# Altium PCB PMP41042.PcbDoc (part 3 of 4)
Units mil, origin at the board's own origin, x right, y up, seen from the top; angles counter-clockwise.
Board outline 9847.6 x 4445 mil, 6 copper layers (Top Layer, Layer 1, Layer 2, Layer 3, Layer 4, Bottom Layer), stack 32.112 mil thick; 329 components, 129 nets, 1246 pads, 863 vias.
Unrouted connection lines stored in the file: 6.
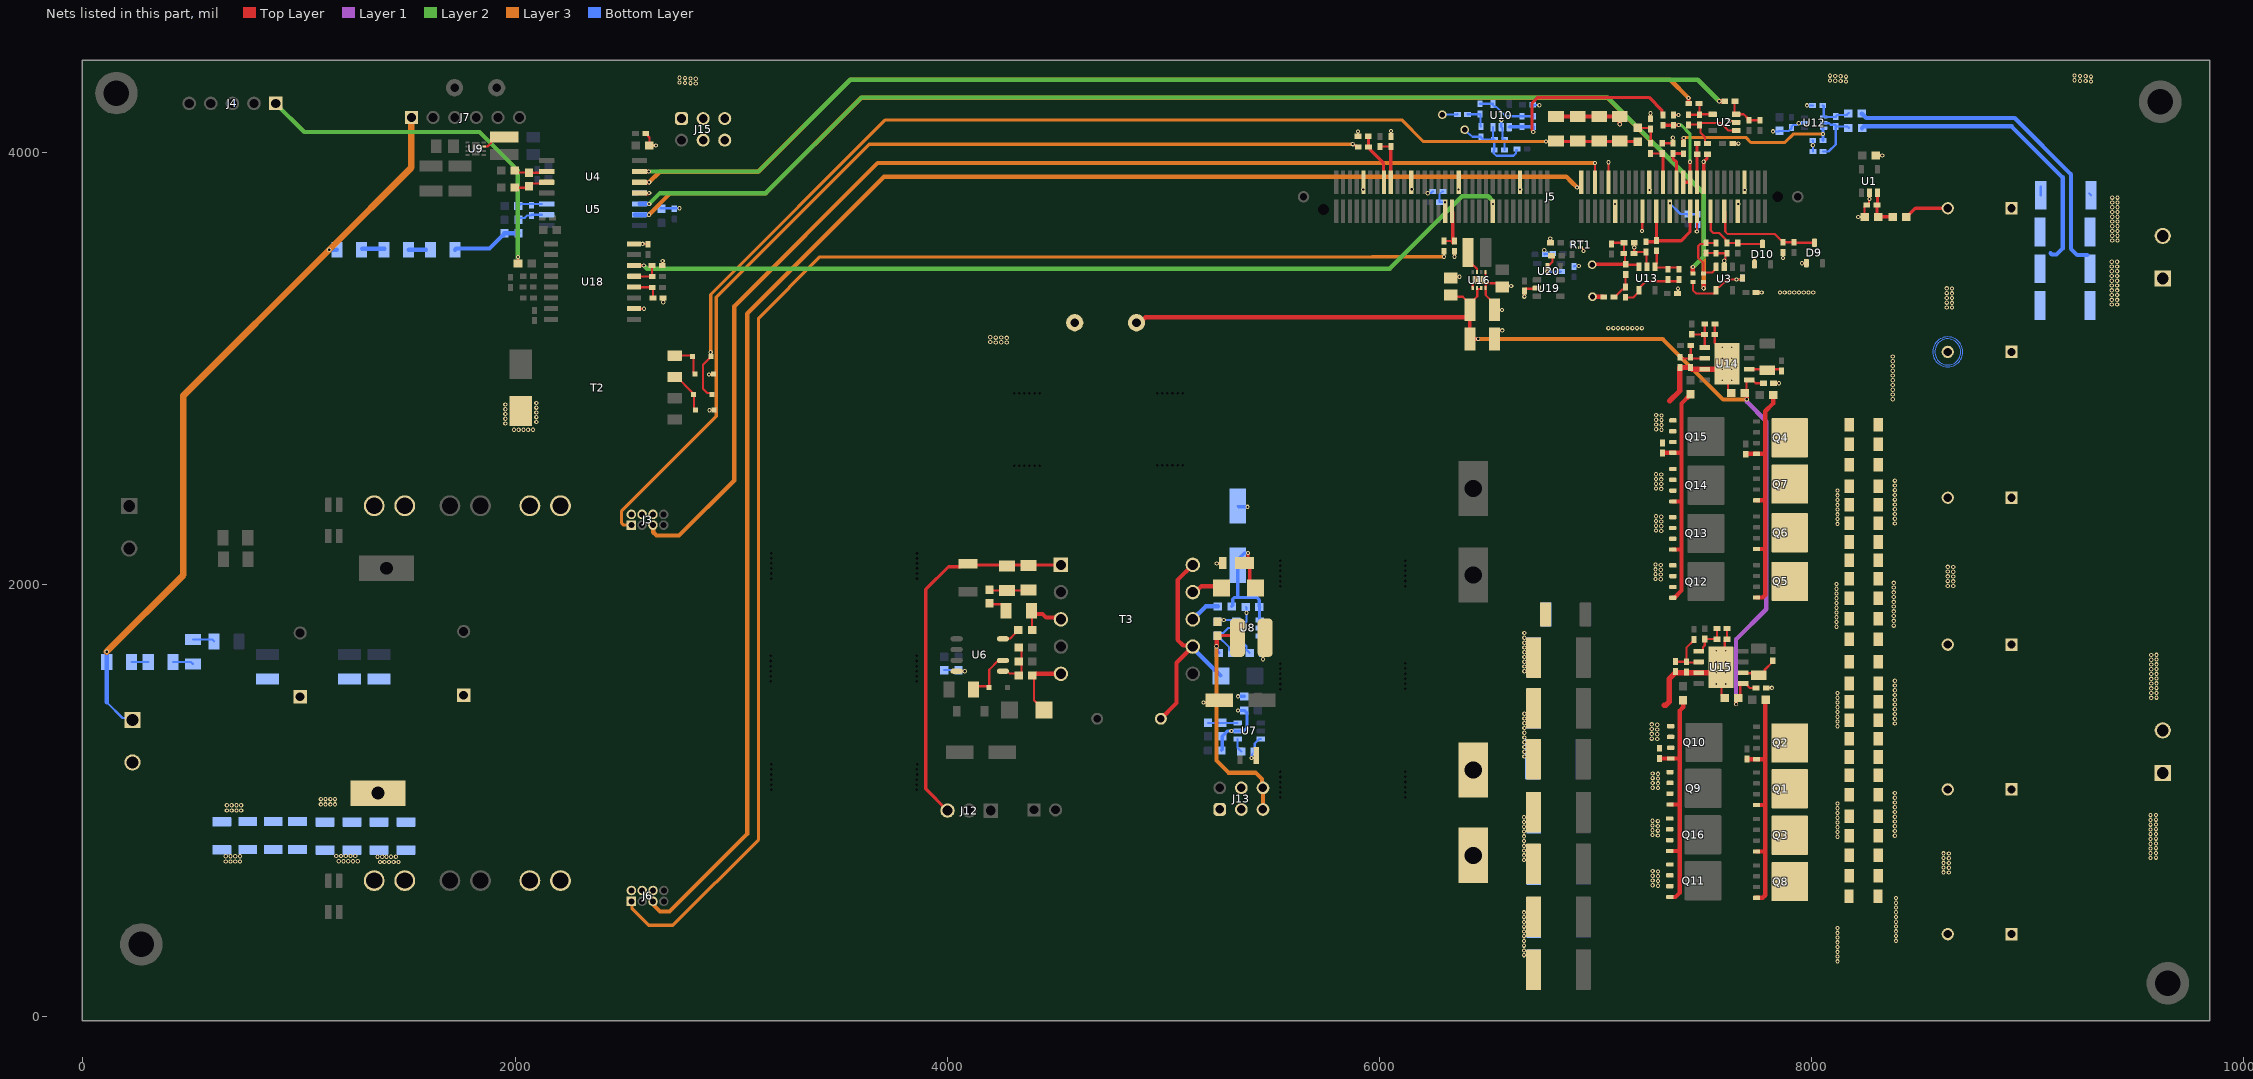
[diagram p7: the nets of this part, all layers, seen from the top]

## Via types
v1: diameter 19.68, hole 10, Top Layer to Bottom Layer, tented both sides, 821 vias
v2: diameter 19.68, hole 7.87, Top Layer to Bottom Layer, 12 vias
v3: diameter 19.68, hole 12, Top Layer to Bottom Layer, tented both sides, 11 vias
v4: diameter 20, hole 10, Top Layer to Bottom Layer, tented both sides, 11 vias
v5: diameter 19.68, hole 7.87, Top Layer to Bottom Layer, tented both sides, 8 vias

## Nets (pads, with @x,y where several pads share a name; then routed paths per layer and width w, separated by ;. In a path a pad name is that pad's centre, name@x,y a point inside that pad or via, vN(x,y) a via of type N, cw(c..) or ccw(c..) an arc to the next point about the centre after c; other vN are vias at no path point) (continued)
12Vs: 12Vs.1 C83.1 C102.2 C104.2 C115.2 C117.2 C128.2 C129.2 C130.1 J13.5 J13.6 J15.5 J15.6 L3.2 R43.2 U14.1 U15.1 U16.2 U16.3 | length 6313.6
  Top Layer w10: C130.1@6334.09,3352.28 6354.09,3332.28 6386.65,3332.28 C128.2@6419.09,3299.84 ; C129.2@6419.09,3138.11 C129.2@6419.92,3137.28 ; C128.2@6419.09,3262.87 C128.2@6419.09,3272.28 C128.2@6419.09,3299.84 ; U16.3@6471.49,3368.54 6453.7,3368.54 6453.7,3334.45 C128.2@6419.09,3299.84 ; C115.2@7651.5,1464.69 C115.2@7661.5,1474.69 7671.06,1484.25 7671.06,1533.86 7676.89,1539.69 7698.62,1539.69 7704.45,1533.86 7704.45,1531.34 7713.5,1522.28 C117.2@7744.25,1522.28 ; C102.2@7701.5,2877.28 C102.2@7691.5,2887.28 7699.41,2895.2 7699.41,2941.46 7705.24,2947.28 U14.1@7713.19,2947.28 7726.97,2947.28 7741.97,2932.28 C104.2@7777.87,2932.28
  Top Layer w15: v3(5246.61,1714.33) v3@5247.51,1715.22 ; R43.2@5247.51,1760.22 R43.2@5251.61,1764.33 5323.66,1764.33 L3.2@5343.66,1744.33 ; C129.2@6419.09,3138.11 C128.2@6419.09,3262.87
  Top Layer w20: 12Vs.1@4876.5,3212.28 4892.73,3212.28 4917.73,3237.28 6403.5,3237.28 6419.09,3252.87 C128.2@6419.09,3272.28 ; v3@5247.51,1715.22 R43.2@5247.51,1760.22 ; C129.2@6419.92,3137.28 v3(6457.32,3137.28) ; v3(7651.5,1447.28) C115.2@7651.5,1464.69 ; v3(7701.5,2857.28) C102.2@7701.5,2877.28
  Layer 1 w20: v3(7651.5,1447.28) 7651.5,1746.5 7791.5,1886.5 7791.5,2756.26 7701.5,2846.26 v3(7701.5,2857.28)
  Layer 3 w20: v3(5246.61,1714.33) 5246.61,1185.65 5302.26,1130 5427.26,1130 5457.26,1100 5457.26,1063.68 J13.6@5461.61,1059.33 J13.5@5461.61,959.33 ; v3(6457.32,3137.28) 7311.5,3137.28 7591.5,2857.28 v3(7701.5,2857.28)
  Bottom Layer w15: v3(5246.61,1714.33) v3@5247.51,1713.43 ; C83.1@5247.51,1693.43 C83.1@5256.61,1684.33
  Bottom Layer w20: C83.1@5247.51,1693.43 v3@5247.51,1713.43
18V: C68.1 C69.1 C81.1 D5.1 D7.1 U8.4 U8.5 | length 710.7
  Top Layer w15: v1(5392,2147) 5392,2114.72 D7.1@5376.61,2099.33 5376.79,2099.33 5400.35,2075.77 D5.1@5400.35,1984.33
  Bottom Layer w15: C69.1@5316.45,1899.33 5321.61,1904.49 5321.61,1932.65 5329.96,1941 5346,1941 ; v1(5392,2147) 5377.4,2147 5345,2114.6 C68.1@5345,2090.19 5345,1942 5346,1941 ; C81.1@5444.96,1899.33 5444.96,1929.04 5433,1941 5346,1941 ; C81.1@5445.5,1897 C81.1@5446.28,1896.21 ; U8.5@5445.74,1799.33 U8.4@5445.74,1836.73 C81.1@5445.74,1898.54
48Vo+: C41.1 C44.1 C46.1 C47.1 C48.1 C49.1 C50.1 C51.1 C52.1 C53.1 C54.1 C55.1 C56.1 C57.1 C58.2 C59.2 C60.1 C61.2 C62.2 C63.2 C64.2 C76.1 C77.1 C87.1 C163.1 C164.1 C186.1 C187.1 C188.1 C189.1 C190.1 J10.1 J10.2 Q1.5 Q1.6 Q1.7 Q1.8 Q1.9@7900.04,1055.16 Q2.5 Q2.6 Q2.7 Q2.8 Q2.9@7900.04,1267.28 Q3.5 Q3.6 Q3.7 Q3.8 Q3.9@7900.04,840.16 Q4.5 Q4.6 Q4.7 Q4.8 Q4.9@7900.04,2680.16 Q5.5 Q5.6 Q5.7 Q5.8 Q5.9@7900.04,2015.16 Q6.5 Q6.6 Q6.7 Q6.8 Q6.9@7900.04,2240.16 Q7.5 Q7.6 Q7.7 Q7.8 Q7.9@7900.04,2465.16 Q8.5 Q8.6 Q8.7 Q8.8 Q8.9@7900.04,625.16 R3.2 | length 195.6
  Top Layer w15: R3.2@8449.62,3710.41 8449.62,3711.43 8454.17,3715.98 8455.2,3715.98 8481.5,3742.28 C59.2@8631.46,3742.28
  other v1: 8121.5,256.23 8121.5,278.24 8121.5,300.24 8121.5,322.25 8121.5,344.26 8121.5,366.27 8121.5,388.28 8121.5,410.28 8636.5,667.28 8611.5,668.27 8636.5,689.29 8611.5,690.28 8636.5,711.3 8611.5,712.28 8636.5,733.31 8611.5,734.29 9570,734.99 9595.5,736.24 8636.5,755.32 8611.5,756.3 9570,757 9595.5,758.24 9570,779.01 9595.5,780.25 9570,801.02 9595.5,802.26 9570,823.02 9595.5,824.27 8121.5,833.23 9570,845.03 9595.5,846.28 8121.5,855.24 9570,867.04 9595.5,868.28 8121.5,877.24 9570,889.05 9595.5,890.29 8121.5,899.25 9570,911.06 9595.5,912.3 8121.5,921.26 9570,933.06 9595.5,934.31 8121.5,943.27 8121.5,965.28 8121.5,987.28 8121.5,1344.25 8121.5,1366.26 8121.5,1388.27 8121.5,1410.28 8121.5,1432.28 8121.5,1454.29 8121.5,1476.3 9573,1475.98 9598,1476.98 8121.5,1498.31 9573,1497.99 9598,1498.99 9573,1520 9598,1521 9573,1542.01 9598,1543.01 9573,1564.02 9598,1565.02 9573,1586.02 9598,1587.02 9573,1608.03 9598,1609.03 9573,1630.04 9598,1631.04 9573,1652.05 9598,1653.05 9573,1674.06 9598,1675.06 8116.5,1805.28 8116.5,1827.28 8116.5,1849.29 8116.5,1871.3 8116.5,1893.31 8116.5,1915.32 8116.5,1937.32 8116.5,1959.33 8116.5,1981.34 8656.5,1993.27 8631.5,1994.25 8116.5,2003.35 8656.5,2015.28 8631.5,2016.26 8656.5,2037.28 8631.5,2038.27 8656.5,2059.29 8631.5,2060.28 8656.5,2081.3 8631.5,2082.28 8121.5,2281.26 8121.5,2303.27 8121.5,2325.28 8121.5,2347.28 8121.5,2369.29 8121.5,2391.3 8121.5,2413.31 8121.5,2435.32 8651.5,3282.28 8626.5,3283.27 8651.5,3304.29 8626.5,3305.28 8651.5,3326.3 8626.5,3327.28 8651.5,3348.31 8626.5,3349.29 8651.5,3370.32 8626.5,3371.3
48Vo-: J11.1 J11.2 R46.2 R49.2 R50.2 R54.2 R72.1 | length 1528.7
  Bottom Layer w10: R50.2@9285.47,3810.91 R50.2@9294.09,3802.28
  Bottom Layer w20: R72.1@8233,4180 8233.98,4180 8253.98,4160 8941,4160 9202,3899 9202,3554 9230,3526 R46.2@9276.55,3526
  other v1: 9390.47,3296.22 9415.47,3296.22 9390.47,3318.23 9415.47,3318.23 9390.47,3340.24 9415.47,3340.24 9390.47,3362.24 9415.47,3362.24 9390.47,3384.25 9415.47,3384.25 9390.47,3406.26 9415.47,3406.26 9390.47,3428.27 9415.47,3428.27 9390.47,3450.28 9415.47,3450.28 9390.47,3472.28 9415.47,3472.28 9390.47,3494.29 9415.47,3494.29 9392.6,3593.11 9417.6,3593.11 9392.6,3615.12 9417.6,3615.12 9392.6,3637.13 9417.6,3637.13 9392.6,3659.13 9417.6,3659.13 9392.6,3681.14 9417.6,3681.14 9392.6,3703.15 9417.6,3703.15 9392.6,3725.16 9417.6,3725.16 9392.6,3747.17 9417.6,3747.17 9392.6,3769.17 9417.6,3769.17 9392.6,3791.18 9417.6,3791.18
Bot_FET_FAULT1: J3.1 R102.1 | length 4538.5
  Top Layer w10: v1(5877,4038.84) 5878.78,4038.84 5885.22,4032.4 5892.58,4032.4 R102.1@5896.29,4028.69
  Layer 3 w15: J3.1@2537.99,2275.39 2537.62,2275.77 2502.23,2275.77 2493,2285 2493,2341 2931.5,2779.5 2931.5,3330.5 3639,4038 5876.16,4038 v1(5877,4038.84)
Bot_FET_FAULT2: J6.1 R97.1 | length 6548.7
  Top Layer w10: v1(6300,3517.44) R97.1@6300,3543.03
  Layer 3 w15: J6.1@2538.39,535.24 2541.52,532.1 2541.52,499.48 2618,423 2730,423 3127,820 3127,3234 3410,3517 5967.46,3517 5967.9,3517.44 v1(6300,3517.44)
Bot_FET_PWM1: J3.5 J5.51 | length 5674.4
  Top Layer w10: J5.51@6998.03,3862.28 v1(6998,3952)
  Layer 3 w20: J3.5@2637.99,2275.39 2639.1,2274.28 2639.1,2242.9 2654.8,2227.2 2758.8,2227.2 3014,2482.4 3014,3288 3678,3952 v1(6998,3952)
Bot_FET_PWM2: J5.55 J6.5 | length 7184.1
  Top Layer w15: v1(6916,3838) 6916.9,3838.9 6925.43,3838.9 6935.04,3848.51 J5.55@6935.04,3862.28
  Layer 3 w20: J6.5@2638.39,535.24 2643,530.63 2643,514.72 2670.72,487 2715,487 3074,846 3074,3254 3708,3888 6866,3888 6888.93,3865.07 v1(6916,3838)
COIL_PRI_N: C132.2 C133.1 pad.1@6395,4106 R55.1 R58.2 U10.3 | length 424.4
  Bottom Layer w10: pad.1@6395,4106 6396.57,4101.18 6397.31,4098.9 6399.56,4096.65 6431.61,4073.38 C132.2@6471,4073.38 6471,4069.44 6480.44,4060 C133.1@6527,4060 ; U10.3@6527,4117.73 C133.1@6527,4060 ; C133.1@6530.38,4051 6527,4054.38 C133.1@6527,4060 ; R55.1@6638,4011 6632.86,4011 6632.24,4010.38 6632.24,3996.24 6621,3985 6542,3985 6530,3997 6530,4009.62 R58.2@6532.38,4012 6532.38,4051 6532.38,4059 C133.1@6533.38,4060 C133.1@6527,4060
COIL_PRI_P: pad.1@6292,4175 R56.1 | length 70.6
  Bottom Layer w10: pad.1@6292,4175 6293,4176 6360.76,4176 R56.1@6361.76,4177
COIL_SEC_N: C89.1 C95.2 pad.1@6985,3481 R30.1 R31.2 U13.3 | length 366
  Top Layer w10: 7088.94,3582.28 C89.1@7133.23,3582.28 7133.23,3533.66 R31.2@7131.85,3532.28 7137.28,3526.85 C95.2@7137.28,3490 ; C95.2@7137.28,3480.91 7194.88,3480.91 7201.69,3474.09 U13.3@7201.69,3471.42
  Top Layer w15: pad.1@6985,3481 6986.62,3482.62 7137.28,3482.62 C95.2@7141,3482.62
COIL_SEC_P: pad.1@6987,3333 R66.1 | length 52.2
  Top Layer w10: pad.1@6987.62,3333 pad.1@6988.62,3332 ; R66.1@7038,3332 R66.1@7039,3331
  Top Layer w20: pad.1@6988.62,3332 R66.1@7038,3332
DGND: C3.2 C18.2 C26.2 C32.2 C33.2 C34.2 C37.2 C38.2 C39.2 C41.2 C44.2 C45.2 C46.2 C47.2 C48.2 C49.2 C50.2 C51.2 C52.2 C53.2 C54.2 C55.2 C56.2 C57.2 C58.1 C59.1 C60.2 C61.1 C62.1 C63.1 C64.1 C68.2 C69.2 C71.2 C72.2 C76.2 C77.2 C80.2 C81.2 C82.2 C83.2 C87.2 C89.2 C92.1 C93.1 C94.1 C97.2 C98.2 C99.2 C100.2 C102.1 C103.1 C104.1 C107.2 C108.2 C109.1 C110.2 C111.1 C112.1 C114.1 C115.1 C116.2 C117.1 C122.2 C123.2 C125.1 C126.2 C127.2 C128.1 C129.1 C130.2 C131.2 C133.2 C134.2 C135.2 C139.1 C140.1 C142.2 C143.2 C144.2 C145.2 C146.2 C149.2 C150.2 C151.2 C163.2 C164.2 C186.2 C187.2 C188.2 C189.2 C190.2 D3.2 D4.2 D7.2 D9.1 D10.1 DGND.1 J3.2 J3.4 J3.6 J5.7 J5.10 J5.19 J5.22 J5.35 J5.38 J5.46 J5.47 J5.65 J5.83 J5.97 J5.111 J6.2 J6.4 J6.6 J13.1 J13.3 J13.4 J15.1 J15.3 J15.4 Q9.1 Q9.2 Q9.3 Q10.1 Q10.2 Q10.3 Q11.1 Q11.2 Q11.3 Q12.1 Q12.2 Q12.3 Q13.1 Q13.2 Q13.3 Q14.1 Q14.2 Q14.3 Q15.1 Q15.2 Q15.3 Q16.1 Q16.2 Q16.3 R5.1 R10.1 R11.1 R12.1 R13.1 R29.1 R31.1 R44.1 R45.1 R46.1 R49.1 R50.1 R51.1 R52.1 R54.1 R58.1 R70.1 R79.1 R82.1 R92.1 R93.1 RT1.1 T3.8 U1.2 U2.2 U3.2 U4.5 U5.5 U7.2 U8.2 U10.2 U12.2 U13.2 U14.7 U14.9@7609.84,3022.28 U15.7 U15.9@7581.5,1617.28 U16.1 U16.4 U16.5 U16.9@6461.97,3409.88 U18.2 U18.8 U19.2 U20.2 | length 8376.9
  Top Layer w10: U18.2@2551.02,3277.28 v1(2596.5,3277.28) ; U18.8@2551.02,3577.28 v1(2590.47,3577.28) 2615.47,3577.28 C140.1@2615.47,3575.91 ; U4.5@2570.04,3807.28 2615.47,3807.28 v1(2620.47,3812.28) ; C38.2@2600.47,4087.28 C38.2@2604.41,4087.28 ; C38.2@2611.13,4094 C38.2@2604.41,4087.28 ; C32.2@2625.08,4029.69 C32.2@2632.6,4029.69 ; v1(2651.5,4032.28) 2635.94,4032.28 2633.35,4034.88 2630.75,4032.28 C32.2@2621.97,4032.28 2621.97,4069.72 C38.2@2604.41,4087.28 ; C146.2@2681.5,3477.28 2683,3478.79 v1(2683,3498) ; C145.2@2685.12,3327.28 2685.47,3326.93 v1(2685.47,3307.28) ; v1(2898,2973) 2899,2974 2917.61,2974 D4.2@2918.61,2975 ; v1(2900,2807) 2901,2808 2914.53,2808 D3.2@2916.81,2810.28 ; v1(5186.61,1454.33) 5249.76,1454.33 C71.2@5259.76,1464.33 ; v1(5248,2098) 5274.89,2098 D7.2@5276.22,2099.33 ; v1(5901,4097) 5901,4076.09 C135.2@5901.5,4075.59 ; v1(5926,3829) 5926.58,3829.58 5926.58,3861.7 J5.111@5927.17,3862.28 ; C134.2@6054.09,4074.53 v1(6054.09,4100.12) ; J5.97@6147.64,3862.28 6148.82,3861.1 6148.82,3831.18 v1(6150,3830) ; C130.2@6330,3420 6335.34,3425.34 v1(6371.38,3425.34) ; v1(6348.19,3517.44) C127.2@6348.19,3543.03 ; v1(6367,3829) 6367.56,3829.56 6367.56,3861.73 J5.83@6368.11,3862.28 ; U16.1@6432.44,3372.48 6432.52,3372.56 6432.52,3394.21 U16.9@6444.25,3405.94 ; U16.9@6469.09,3402.28 U16.9@6471.11,3404.3 ; v2(6483.62,3409.88) 6483.62,3417.76 6491.42,3425.55 6491.42,3447.2 U16.5@6491.5,3447.28 ; U16.9@6485.28,3402.56 U16.9@6485.28,3394.69 ; U16.4@6492.99,3379.09 6492.99,3386.97 U16.9@6485.28,3394.69 ; U16.4@6493.07,3379.02 6493.07,3357.36 6493.15,3357.28 6493.15,3339.96 6533.27,3299.84 C128.1@6533.27,3272.28 6534.55,3271 v1(6568,3271) ; C129.1@6534.09,3137.28 6534.09,3156.41 6554.69,3177 v1(6569,3177) ; v1(6610.47,3382.28) 6574.09,3382.28 C131.2@6569.09,3377.28 6551.69,3394.69 U16.9@6485.28,3394.69 ; J5.65@6651.57,3862.28 6651.79,3862.07 6651.79,3829.21 v1(6652,3829) ; v1(6671.5,3333.07) C144.2@6671.5,3358.66 6671.5,3362.6 6678.31,3369.41 6727.09,3369.41 U19.2@6729.96,3372.28 ; v1(6778,3447) 6778,3471.88 6777.6,3472.28 6778.58,3472.28 6801.5,3495.2 C143.2@6801.5,3522.28 ; v1(6791.5,3602.28) 6791.5,3583.66 C97.2@6792.87,3582.28 ; RT1.1@6931.5,3559.49 6933.39,3557.6 6938.31,3557.6 6943.15,3552.76 6943.15,3545.85 v1(6945,3544) ; v1(7060.69,3955) 7060.85,3954.83 7060.85,3862.45 J5.47@7061.02,3862.28 ; v1(7091.5,3762.28) 7092.01,3761.77 7092.01,3728.94 J5.46@7092.52,3728.43 ; C89.2@7180.47,3582.28 v1(7180.47,3560.63) 7180.47,3533.66 R31.1@7179.09,3532.28 7183.03,3532.28 7190.47,3539.72 C116.2@7234.09,3539.72 7236.59,3537.22 7236.59,3473.92 U13.2@7239.09,3471.42 ; v1(7216.5,3637.28) 7217.5,3638.29 7217.5,3727.42 J5.38@7218.5,3728.43 ; J5.35@7250,3862.28 7250.75,3861.54 7250.75,3828.03 v1(7251.5,3827.28) ; C26.2@7256,4156.62 v1(7256,4182.21) ; C139.1@7310,4043.21 C110.2@7358.97,4043.21 ; C110.2@7359,4043.24 v1(7359,4068.83) ; C109.1@7362.65,4173.24 7363.41,4174 v1(7385,4174) ; C94.1@7380.12,3347.28 7383,3350.17 v1(7383,3370) ; v1(7470,3635) 7470.24,3635.24 7470.24,3728.19 J5.22@7470.47,3728.43 ; R29.1@7504.69,3538.66 7511.5,3531.85 R29.1@7511.5,3530.04 ; R29.1@7511.65,3535.32 7557.44,3535.32 C45.2@7559.09,3533.66 C112.1@7609.09,3533.66 7602.28,3526.85 7602.28,3507.31 7596.69,3501.72 v1(7596.69,3499.09) U3.2@7596.69,3470.55 ; R82.1@7553.74,3207.28 7552.52,3206.06 C107.2@7552.52,3157.28 7552.52,3117.99 7571.46,3099.06 v5(7588.19,3099.06) ; U15.9@7581.5,1617.28 7583.82,1614.96 7583.82,1488.39 7597.52,1474.69 C115.1@7598.5,1474.69 ; v5(7603.15,1694.06) 7599.37,1697.83 7599.37,1740.47 7606.18,1747.28 R93.1@7610.12,1747.28 C122.2@7610.12,1797.28 ; v1(7621.5,4147.28) 7623.35,4145.43 7645.75,4145.43 U2.2@7651.5,4139.69 ; C102.1@7628.5,2887.28 7627.52,2887.28 7613.82,2900.98 7613.82,2930.83 7628.5,2945.51 v5(7631.5,2945.51) ; C34.2@7636.5,4042.28 7637.09,4041.69 7661.49,4041.69 v1(7662.09,4041.09) ; J5.10@7659.45,3728.43 7660.47,3729.45 7660.47,3761.26 v1(7661.5,3762.28) ; J5.7@7690.94,3862.28 7691.22,3862.01 7691.22,3827.56 v1(7691.5,3827.28) ; v1(7736.5,3512.28) 7736.59,3512.19 7736.59,3482.38 D10.1@7736.69,3482.28 ; C39.2@7744.29,3352.28 v1(7769.88,3352.28) ; C117.1@7791.5,1522.28 v1(7817.09,1522.28) ; C104.1@7825.12,2932.28 v1(7850.71,2932.28) ; v1(7869.09,3511.69) C114.1@7869.09,3537.28 ; v1(7956.5,3487.28) 7956.75,3487.54 7976.44,3487.54 D9.1@7976.69,3487.8 ; v1(8216.69,3701.59) R5.1@8246.22,3701.59 8246.22,3750.47 8253.03,3757.28 C18.2@8256.5,3757.28 8260.43,3757.28 8267.24,3764.09 8267.24,3783.4 v1(8268.62,3784.78) U1.2@8268.62,3813.33 ; C3.2@8298.54,3985.98 v1(8328.07,3985.98)
  Top Layer w15: v1(7501.5,3957.28) v1@7501.97,3956.81 ; J5.19@7501.97,3862.28 7501.73,3862.52 7501.73,3956.57 v1@7501.97,3956.81 ; C111.1@7518.74,3992.28 7516.49,3990.03 7516.49,3971.33 v1@7501.97,3956.81
  Top Layer w20: R10.1@6820,4164.95 R10.1@6818.28,4166.67 R12.1@6918.28,4166.67 R11.1@7018.28,4166.67 R13.1@7113.28,4166.67 7113,4166.39 v1(7113,4131)
  Top Layer w25: 7318,1442 7327.36,1442 7342,1456.64 7342,1563 7371.28,1592.28 U15.7@7478.15,1592.28 U15.9@7559.25,1592.28 ; 7344.08,2850.08 7391.5,2897.5 R79.1@7391.5,3005.04 C108.2@7441.5,3005.04 7441.5,3004.09 7448.31,2997.28 U14.7@7506.5,2997.28 7584.84,2997.28 U14.9@7609.84,3022.28
  Bottom Layer w0.5: 8691.59,3077.28 ccw(c8631.46,3077.28) 8691.59,3077.28 ; 8700.88,3077.28 ccw(c8631.46,3077.28) 8700.88,3077.28
  Bottom Layer w10: U5.5@2553.66,3812.28 U5.5@2575.47,3812.28 v1(2620.47,3812.28) ; C37.2@2672.47,3740.37 2674.39,3742.28 v1(2760.47,3742.28) ; C83.2@5319.6,1684.33 5318.62,1684.33 5304.92,1698.03 5304.92,1710.04 5251.61,1763.34 R45.1@5251.61,1764.33 5263.91,1776.63 5278.91,1776.63 5301.61,1799.33 U8.2@5337.48,1799.33 5343.6,1805.45 5362.88,1805.45 5385,1827.57 v1(5385,1870) 5385,1894.5 C81.2@5382.5,1897 ; C68.2@5345,2363.81 C68.2@5348.81,2360 ; v1(6224.22,3811.59) 6226.07,3813.45 6240.69,3813.45 6240.94,3813.19 C126.2@6247.76,3820 ; v1(6565,4150) 6564.7,4149.7 6564.7,4118.03 U10.2@6564.4,4117.73 6570,4112.13 6570,4066.81 6576.81,4060 C133.2@6580.62,4060 6579.62,4059 R58.1@6579.62,4012 ; C125.1@6710.24,4221 6711.24,4220 6740,4220 v1(6741,4219) ; v1(6763.86,3547.8) 6764.19,3547.46 6764.19,3529.43 6764.53,3529.09 6766.12,3530.69 6804.9,3530.69 C151.2@6806.5,3532.28 ; v1(6778,3447) 6779.44,3448.44 6838.32,3448.44 U20.2@6839.76,3449.88 ; C149.2@6901.5,3472.28 6904.21,3475 v1(6923,3475) ; v1(7470,3635) 7471.85,3636.85 7471.85,3665.04 C103.1@7474.09,3667.28 ; v1(7823,4098) 7850.21,4098 C93.1@7852.72,4100.5 7895.91,4100.5 7907.72,4112.31 C92.1@7907.72,4116.25 7907.72,4120.19 7914.53,4127 7931.22,4127 7940.16,4135.94 v1(7941.85,4135.94) 7965.55,4135.94 U12.2@7968.43,4138.81 ; v1(7979.88,4218.5) C99.2@8005.47,4218.5 C99.2@8006.2,4217.77 ; C98.2@8006.2,4055.23 8006.9,4054.52 v1(8006.9,4033.57) C100.2@8006.9,4004.64 ; R50.1@9061.81,3802.28 R50.1@9061.81,3843.62
  Bottom Layer w15: C82.2@5269.6,1232.87 5273.11,1236.38 R44.1@5273.11,1297.87 5273.11,1298.86 5286.81,1312.56 5287.79,1312.56 5298.11,1322.87 v1(5315.43,1322.87) U7.2@5343.97,1322.87 5373.11,1322.87 5388.11,1337.87 5388.11,1404.88 C80.2@5375.11,1417.87 v1(5345.59,1417.87) ; v1(5345.59,1482.87) C72.2@5375.11,1482.87 ; C68.2@5348.81,2360 v1(5390,2360)
  Bottom Layer w20: T3.8@5136.73,1839.33 5196.73,1899.33 C69.2@5253.46,1899.33 ; R70.1@8234.5,4113 8242.5,4121 8927,4121 9163,3885 9163,3556 9135,3528 9113,3528 9107,3534
  other v1: 8391.5,351.26 8391.5,373.27 8391.5,395.28 8391.5,417.28 8391.5,439.29 8391.5,461.3 8391.5,483.31 8391.5,505.32 8391.5,527.32 8391.5,549.33 7290.47,606.26 7265.47,608.23 7290.47,628.27 7265.47,630.24 7290.47,650.28 7265.47,652.24 7290.47,672.28 7265.47,674.25 8386.44,837.36 7289.45,839.25 7264.45,841.22 8386.44,859.37 7289.45,861.26 7264.45,863.23 8386.44,881.38 7289.45,883.27 7264.45,885.24 8386.44,903.38 7289.45,905.28 7264.45,907.24 8386.44,925.39 8386.44,947.4 8386.44,969.41 8386.44,991.42 8386.44,1013.42 8386.44,1035.43 7290.47,1058.27 7265.47,1060.24 7290.47,1080.28 7265.47,1082.24 7290.47,1102.28 7265.47,1104.25 7290.47,1124.29 7265.47,1126.26 7286.5,1285.28 7261.5,1287.24 7286.5,1307.28 7261.5,1309.25 7286.5,1329.29 7261.5,1331.26 7286.5,1351.3 7261.5,1353.27 8386.5,1357.24 8386.5,1379.25 8386.5,1401.26 8386.5,1423.27 8386.5,1445.28 8386.5,1467.28 8386.5,1489.29 8386.5,1511.3 8386.5,1533.31 8386.5,1555.32 8381.5,1810.28 8381.5,1832.28 8381.5,1854.29 8381.5,1876.3 8381.5,1898.31 8381.5,1920.32 8381.5,1942.32 8381.5,1964.33 8381.5,1986.34 8381.5,2008.35 7303.16,2024.69 7278.16,2026.66 7303.16,2046.7 7278.16,2048.67 7303.16,2068.71 7278.16,2070.67 7303.16,2090.71 7278.16,2092.68 7305.47,2248.27 7280.47,2250.24 7305.47,2270.28 7280.47,2272.24 8386.5,2283.27 7305.47,2292.28 7280.47,2294.25 8386.5,2305.28 7305.47,2314.29 7280.47,2316.26 8386.5,2327.28 8386.5,2349.29 8386.5,2371.3 8386.5,2393.31 8386.5,2415.32 8386.5,2437.32 7305.47,2443.27 7280.47,2445.24 8386.5,2459.33 7305.47,2465.28 7280.47,2467.24 8386.5,2481.34 7305.47,2487.28 7280.47,2489.25 7305.47,2509.29 7280.47,2511.26 7306.5,2717.28 7281.5,2719.25 7306.5,2739.29 7281.5,2741.26 7306.5,2761.3 7281.5,2763.27 7306.5,2783.31 7281.5,2785.28 8376.5,2858.23 8376.5,2880.24 8376.5,2902.24 8376.5,2924.25 8376.5,2946.26 8376.5,2968.27 8376.5,2990.28 8376.5,3012.28 8376.5,3034.29 8376.5,3056.3 4275.47,3120.28 4224.5,3121.28 4250.47,3122.24 4199.5,3123.25 4275.47,3142.28 4224.5,3143.29 4250.47,3144.25 4199.5,3145.26 7060.43,3187.28 7083.42,3187.28 7105.43,3187.28 7127.44,3187.28 7149.45,3187.28 7171.46,3187.28 7193.46,3187.28 7215.47,3187.28 7854.45,3352.28 7876.46,3352.28 7898.46,3352.28 7920.47,3352.28 7942.48,3352.28 7964.49,3352.28 7986.5,3352.28 8008.5,3352.28 2836.5,4319.28 2811.5,4321.25 2786.5,4322.28 2761.5,4324.25 8160.5,4329.28 9294.5,4329.28 8135.5,4331.25 9269.5,4331.25 8110.9,4332 9243.18,4332.62 8085.9,4333.96 9218.18,4334.59 2836.5,4341.29 2811.5,4343.26 2786.5,4344.29 2761.5,4346.26 8160.5,4351.29 9294.5,4351.29 8135.5,4353.26 9269.5,4353.26 8110.9,4354 9243.18,4354.63 8085.9,4355.97 9218.18,4356.6
  other v2: 7559.84,1591.69 7603.15,1591.69 7559.84,1642.87 7603.15,1642.87 7588.19,2996.69 7631.5,2996.69 7588.19,3047.87 7631.5,3047.87 6440.31,3409.88
  other v5: 7559.84,1540.51 7603.15,1540.51 7559.84,1694.06 7588.19,2945.51 7631.5,3099.06
GaN_SW1: GaN_SW1.1 T2.2
  other v1: 1994.45,2717.28 2016.46,2717.28 2038.46,2717.28 2060.47,2717.28 2082.48,2717.28 1955,2745.98 2098.46,2753.27 1955,2767.99 2098.46,2775.28 1955,2790 2098.46,2797.28 1955,2812.01 2098.46,2819.29 1955,2834.02 2098.46,2841.3
GaN_SW2: C1.1 C5.1 C9.1 C15.1 C90.1 C113.1 C118.1 C119.1 GaN_SW2.1
  other v1: 1374.98,716 1394.98,716 1415.99,716 1438,716 1460.01,716 660.98,719 682.99,719 705,719 727,719 1183.87,719.59 1205.87,719.59 1227.88,719.59 1249.89,719.59 1271.9,719.59 1363.13,740.41 1385.09,740.41 1405.09,740.41 1426.11,740.41 1448.12,740.41 660.98,743.02 682.99,743.02 705,743.02 727,743.02 1171.98,744 1193.98,744 1215.99,744 1238,744 1260.01,744
HVBUS: C8.HVBUS C11.1 C12.1 C13.1 C66.1 C67.1 C101.1 HVBUS1.1 HVBUS2.1 HVBUS.1 J1.HVBUS J7.1 J12.3 R1.2 R15.2 R32.2 T3.1 | length 5197.3
  Top Layer w15: J12.3@4001.61,954.33 3901,1054.94 3901,1977.86 4006.01,2082.87 4061.85,2082.87 4070.27,2091.3 T3.1@4506.49,2091.3
  Layer 3 w30: v3(110,1690) 465,2045 465,2875.43 v3(1139.57,3550) 1520.47,3930.91 J7.1@1520.47,4162.28
  Bottom Layer w10: 109.92,1455.08 182.55,1382.45 220.78,1382.45 J1.HVBUS@229.09,1374.13 ; R1.2@109.92,1642.28 R1.2@110,1642.36
  Bottom Layer w20: 109.92,1455.08 R1.2@109.92,1642.28 ; R1.2@110,1642.36 v3(110,1690) ; v3(1139.57,3550) R15.2@1175,3550
ISNS_PRI: C25.1 R14.2 R84.1 U2.1 | length 337.5
  Top Layer w10: C25.1@7431.5,4127.44 7433.46,4129.41 7479.53,4129.41 R14.2@7481.5,4127.44 ; R84.1@7518.74,4042.28 7514.8,4042.28 7507.99,4049.09 7507.99,4070.79 7486.5,4092.28 7486.5,4122.44 R14.2@7481.5,4127.44 ; U2.1@7644.09,4102.28 7615.08,4102.28 7580.08,4137.28 7488.31,4137.28 7481.5,4130.47 R14.2@7481.5,4127.44
ISNS_PRI_TANK: C124.1 R53.1 R85.2 U10.1 | length 935.6
  Top Layer w15: v1(6713,4095) 6713,4096.27 6707,4102.27 6707,4229 6733,4255 7249,4255 7308.34,4195.66 7308.34,4177.56 R85.2@7312.65,4173.24
  Bottom Layer w15: U10.1@6601.8,4117.73 6603.31,4119.24 6711.49,4119.24 R53.1@6713,4120.76 v1(6713,4095)
ISNS_PRI_TANK1: C26.1 R6.1 R59.1 | length 124.4
  Top Layer w10: R6.1@7196.28,4113.99 7251.39,4113.99 C26.1@7256,4109.38 7256.5,4108.88 7256.5,4047.5 R59.1@7257,4047
ISNS_SEC: C98.1 R86.1 U12.6 | length 752
  Top Layer w20: R86.1@7409,4041.24 v1(7409,4066.83)
  Layer 3 w15: v1@7409,4068.1 v1@7409,4069 ; v1@7409,4070 7697,4070 7720.44,4046.56 7877.43,4046.56 7916.53,4085.66 v1(8053.44,4085.66)
  Bottom Layer w15: C98.1@8053.44,4055.23 v1(8053.44,4085.66) U12.6@8053.44,4110.35
ISNS_SEC_TANK: C91.1 R64.2 R89.1 U13.1 | length 193.4
  Top Layer w10: R89.1@7284.09,3545.04 7284.09,3486.89 7276.5,3479.29 U13.1@7276.5,3471.42 7280.63,3467.28 7381.28,3467.28 7388.09,3460.47 C91.1@7388.09,3459.94
LLC_Fault: J5.74 U18.6 | length 4177.2
  Top Layer w10: J5.74@6525.59,3728.43 J5.74@6526.04,3728.88 ; J5.74@6526.04,3761.83 v1(6526.5,3762.28)
  Top Layer w15: U18.6@2551.02,3477.28 v1(2595.47,3477.28) ; J5.74@6526.04,3728.88 J5.74@6526.04,3761.83
  Layer 2 w20: v1(2595.47,3477.28) 2610.76,3462 6048,3462 6383.28,3797.28 6504.72,3797.28 6525.6,3776.4 6525.6,3763.18 v1(6526.5,3762.28)
NetC1_2: C1.2 C5.2 C9.2 C15.2 C90.2 C113.2 C118.2 C119.2 pad.2@1365.35,1035
  other v1: 665.98,954.97 687.99,954.97 710,954.97 732,954.98 665.98,978.98 687.99,978.98 710,978.98 732,979 1100.98,983 1122.99,983 1145,983 1167,983.02 1100.98,1007.02 1122.99,1007.02 1145,1007.02 1167,1007.03
NetC2_1: C2.1 C4.1 C6.1 C7.1 C10.1 C14.1 C16.1 C17.1 C19.1 C20.1 C21.1 C22.1 C23.1 C24.1 C27.1 C28.1 pad.2@6435,746.89 pad.2@6435,1141.73
  other v1: 6670.22,284.96 6670.22,306.96 6670.22,328.97 6670.22,350.98 6670.22,372.99 6670.22,395 6670.22,417 6670.22,439.01 6670.22,461.02 6670.22,483.03 6670.22,724.96 6670.22,746.96 6670.22,768.97 6670.22,790.98 6670.22,812.99 6670.22,835 6670.22,857 6670.22,879.01 6670.22,901.02 6670.22,923.03 6671.5,1204.21 6671.5,1226.22 6671.5,1248.23 6671.5,1270.24 6671.5,1292.24 6671.5,1314.25 6671.5,1336.26 6671.5,1358.27 6671.5,1380.28 6671.5,1402.28 6671.5,1599.21 6671.5,1621.22 6671.5,1643.23 6671.5,1665.24 6671.5,1687.24 6671.5,1709.25 6671.5,1731.26 6671.5,1754.25 6671.5,1776.26
NetC18_1: C18.1 R3.1 R5.2 U1.3 | length 182.5
  Top Layer w15: U1.3@8306.02,3813.33 8306.02,3759.57 C18.1@8303.74,3757.28 8303.74,3707.07 R5.2@8309.21,3701.59 8309.9,3702.28 R3.1@8376.5,3702.28
NetC25_2: C25.2 R14.1 R19.2 U2.4 | length 158.5
  Top Layer w10: C25.2@7431.5,4174.69 R14.1@7481.5,4174.69 ; R19.2@7480.12,4227.28 7481.5,4225.91 R14.1@7481.5,4174.69 ; U2.4@7535.83,4177.09 7483.9,4177.09 R14.1@7481.5,4174.69
NetC29_1: C29.1 R16.1 R23.2 U3.4 | length 296.8
  Top Layer w10: R23.2@7451.5,3397.28 7451.5,3362.28 7466.5,3347.28 U3.4@7548.52,3347.28 ; U3.4@7559.29,3370.16 7566.1,3376.97 7573.98,3376.97 7609.29,3412.28 v1(7653.62,3412.28) C29.1@7669.91,3412.28
  Bottom Layer w10: v1(7653.62,3412.28) 7675.12,3412.28 R16.1@7681.5,3418.66
NetC40_1: C40.1 R18.2 U4.2 | length 142.9
  Top Layer w10: R18.2@2001.5,3907.28 2063.2,3907.28 2064.24,3906.25 U4.2@2144,3906.25
NetC40_2: C40.2 R24.2 U4.3 | length 161.2
  Top Layer w10: R24.2@2011.69,3823.58 R24.2@1997.99,3837.28 2058.27,3837.28 C40.2@2063.9,3842.91 C40.2@2059.09,3847.72 ; C40.2@2077.23,3856.25 U4.3@2144,3856.25
NetC42_1: C42.1 R21.2 R25.2 U2.3 | length 188.5
  Top Layer w10: R21.2@7646.34,4237.28 7644.09,4235.04 7644.09,4177.09 U2.3@7651.5,4177.09 7686.69,4177.09 7704.09,4159.69 7704.09,4149.53 C42.1@7754.09,4149.53
NetC43_1: C43.1 R22.2 U5.2 | length 120.3
  Bottom Layer w10: R22.2@2010.47,3697.28 2043.66,3697.28 2054.52,3708.14 2071.33,3708.14 2075.47,3712.28 U5.2@2124.53,3712.28
NetC43_2: C43.2 R28.2 U5.3 | length 116.2
  Bottom Layer w10: R28.2@2015.47,3752.28 R28.2@2018.27,3755.08 ; R28.2@2015.47,3755.08 R28.2@2018.27,3755.08 ; R28.2@2018.43,3755.08 R28.2@2018.27,3755.08 ; U5.3@2124.53,3762.28 2025.47,3762.28 R28.2@2018.27,3755.08
NetC45_1: C45.1 R26.2 R29.2 U3.3 | length 303.8
  Top Layer w10: C45.1@7559.09,3580.91 7513.31,3580.91 R29.2@7511.65,3582.56 7506.38,3577.28 7486.5,3577.28 7476.5,3567.28 7476.5,3512.28 7501.5,3487.28 7501.5,3444.53 7541.14,3444.53 7559.29,3462.68 U3.3@7559.29,3470.55 U3.3@7559.29,3478.43
NetC65_1: C65.1 D12.2 T3.7 T3.10 | length 1056
  Top Layer w15: C65.1@4979.72,1367.43 C65.1@4990.43,1378.15
  Top Layer w20: C65.1@4989.25,1379.33 5061.86,1451.94 5061.86,1638.47 T3.7@5136.73,1713.34 5131.42,1718.65 5092.29,1718.65 5066.61,1744.33 5066.61,2021.18 T3.10@5136.73,2091.3
  Bottom Layer w10: T3.7@5136.73,1706.73 T3.7@5136.73,1713.34
  Bottom Layer w20: T3.7@5136.73,1706.73 D12.2@5264.13,1579.33
NetC66_2: C66.2 R32.1 R33.2 | length 182.9
  Top Layer w10: R33.2@4186.61,1972.32 4365.47,1972.32 C66.2@4368.3,1975.15
NetC73_1: C73.1 D11.1 U6.6 | length 254
  Top Layer w10: C73.1@4105.39,1514.33 4120.39,1529.33 4195,1529.33 4195,1606.44 4237.88,1649.33 U6.6@4258.3,1649.33
NetC74_1: C74.1 R41.2 U6.4 | length 134.9
  Top Layer w10: U6.4@4043.74,1599.33 v1(4081.61,1599.33)
  Bottom Layer w10: C74.1@3986.61,1604.33 R41.2@4051.61,1604.33 4056.61,1599.33 v1(4081.61,1599.33)
NetC75_1: C75.1 R34.1 R40.2 U6.5 | length 222.1
  Top Layer w10: U6.5@4258.3,1599.33 4277.7,1599.33 4287.7,1589.33 4332.32,1589.33 4342.32,1579.33 4343.3,1579.33 4343.46,1579.49 4343.46,1643.03 C75.1@4343.46,1708.03
NetC78_1: C78.1 L1.1 U7.6 | length 143.1
  Top Layer w10: v1(5408.11,1197.87) L1.1@5428.7,1197.87
  Top Layer w20: L1.1@5428.7,1197.87 5430.51,1199.68 L1.1@5430.51,1209.17
  Bottom Layer w8: v1(5408.11,1197.87) 5408.92,1198.68 5408.92,1213.17 C78.1@5423.62,1227.87
  Bottom Layer w10: C78.1@5423.62,1227.87 5423.62,1264.72 5444.37,1285.47 U7.6@5452.24,1285.47
NetC78_2: C78.2 U7.1 | length 65.5
  Bottom Layer w10: U7.1@5343.97,1285.47 5343.97,1244.52 5360.63,1227.87 C78.2@5361.61,1227.87
NetC79_1: C79.1 L3.1 U8.6 | length 220.1
  Top Layer w10: v1(5461.61,1654.33) 5461.61,1744.33 L3.1@5471.61,1754.33
  Bottom Layer w10: U8.6@5445.74,1761.93 5445.74,1700.71 5462.12,1684.33 C79.1@5463.11,1684.33 5461.61,1682.83 v1(5461.61,1654.33)
NetC79_2: C79.2 U8.1 | length 108.7
  Bottom Layer w10: U8.1@5337.48,1761.93 5345.35,1761.93 5352.16,1755.12 5352.16,1747.24 5385.43,1713.97 5385.43,1698.03 5399.13,1684.33 C79.2@5400.11,1684.33
NetC91_2: C91.2 R64.1 R68.2 U13.4 | length 279.8
  Top Layer w10: R68.2@7140.47,3328.66 7175.08,3328.66 7201.69,3355.28 U13.4@7201.69,3363.15 7201.69,3371.02 7234.96,3404.29 C91.2@7379.69,3404.29
NetC95_1: C95.1 R66.2 R68.1 | length 132.1
  Top Layer w10: R66.2@7086.24,3331 7090.18,3331 7125.72,3366.54 7133.66,3366.54 7140.47,3373.35 R68.1@7140.47,3377.28 C95.1@7140.47,3433.66
NetC96_1: C96.1 C100.1 R70.2 U12.5 | length 309
  Bottom Layer w10: C100.1@8054.15,4004.64 8079.74,4004.64 8112.72,4037.62 C96.1@8112.72,4119.87 8117.72,4119.87 8167.83,4119.87 R70.2@8172.72,4114.99 ; U12.5@8057.01,4138.81 U12.5@8059.09,4136.72 ; C96.1@8117.72,4120.19 8117.72,4121.65 8116.1,4123.26 8110.91,4128.46 8089.45,4128.46 8081.97,4135.94 ; U12.5@8059.09,4136.72 8059.88,4135.94 8081.97,4135.94 ; U12.5@8059.09,4136.72 8081.18,4136.72 8081.97,4135.94
NetC96_2: C96.2 C99.1 R72.2 U12.4 | length 178.4
  Bottom Layer w10: C99.1@8052.72,4218.5 8057.01,4214.2 U12.4@8057.01,4164.4 C96.2@8112.72,4164.4 ; C96.2@8112.72,4167.12 8119.09,4173.5 8162.72,4173.5 R72.2@8172.72,4183.5
NetC103_2: C103.2 J5.30 R76.1 | length 186.8
  Top Layer w10: J5.30@7344.49,3728.43 7344.74,3728.68 7344.74,3764.74 v1(7345,3765)
  Bottom Layer w10: v1(7345,3765) 7394.09,3715.91 R76.1@7424.09,3715.91 7425.47,3714.53 C103.2@7474.09,3714.53
NetC105_2: C105.2 C106.1 U14.2 | length 152.4
  Top Layer w10: U14.2@7713.19,2997.28 7854.69,2997.28 7861.5,2990.47 C106.1@7861.5,2989.21
NetC107_1: C107.1 R77.2 R82.2 U14.5 | length 170.4
  Top Layer w10: R77.2@7446.5,3158.66 7447.87,3157.28 C107.1@7505.28,3157.28 ; U14.5@7506.5,3097.28 7506.5,3156.06 C107.1@7505.28,3157.28 ; R82.2@7506.5,3207.28 7506.5,3158.5 C107.1@7505.28,3157.28
NetC108_1: C108.1 R78.2 R79.2 U14.6 | length 172.1
  Top Layer w10: R79.2@7391.5,3052.28 7396.5,3047.28 U14.6@7506.5,3047.28 ; C108.1@7441.5,3052.28 R78.2@7441.5,3107.28
NetC109_2: C109.2 J5.23 J5.25 R85.1 | length 402.9
  Top Layer w15: R85.1@7312.65,4122.06 R85.1@7312.65,4126 C109.2@7362.65,4126 7363.15,4126.5 7385.5,4126.5 v1(7386,4127) ; J5.25@7407.48,3862.28 J5.23@7438.98,3862.28 7438.49,3862.77 7438.49,3956.51 v1(7438,3957)
  Layer 2 w15: v1(7386,4127) 7386.9,4126.1 7398.9,4126.1 7438,4087 v1(7438,3957)
NetC110_1: C110.1 J5.27 R86.2 | length 191.6
  Top Layer w15: J5.27@7375.98,3862.28 7375.98,3955.02 7359,3972 C110.1@7359,3996 7407,3996 R86.2@7409,3994
NetC111_2: C111.2 J5.21 R84.2 | length 176.5
  Top Layer w10: R84.2@7470.63,4041.42 R84.2@7471.5,4042.28
  Top Layer w15: J5.21@7470.63,3866.14 7470.63,3992.28 R84.2@7470.63,4041.42
NetC112_2: C112.2 D10.3 J5.18 R81.1 | length 364.4
  Top Layer w10: J5.18@7534.26,3731.65 7534.26,3639.52 7546.5,3627.28 7573.72,3627.28 7602.28,3598.72 7602.28,3587.72 C112.2@7609.09,3580.91 R81.1@7659.09,3580.91 7663.23,3576.77 D10.3@7774.09,3576.77
NetC114_2: C114.2 D9.3 J5.14 R83.1 | length 536.3
  Top Layer w10: J5.14@7596.61,3732.28 7601.3,3727.6 7601.3,3644.1 7601.46,3643.95 7601.46,3634.54 7613.72,3622.28 7831.34,3622.28 7858.35,3595.28 7862.28,3595.28 7869.09,3588.46 C114.2@7869.09,3584.53 R83.1@7919.09,3584.53 7921.34,3582.28 D9.3@8014.09,3582.28
NetC116_1: C116.1 J5.24 J5.34 R89.2 | length 458.5
  Top Layer w15: C116.1@7234.09,3586.97 7278.78,3586.97 7282.87,3591.06 7282.87,3731.06 J5.34@7281.65,3732.28 ; R89.2@7284.09,3592.28 7396.83,3592.28 7438.33,3633.79 7438.33,3727.78 J5.24@7438.98,3728.43
NetC120_2: C120.2 C121.1 U15.2 | length 182.2
  Top Layer w10: U15.2@7684.84,1589.69 7742.17,1589.69 7756.5,1575.35 7766.34,1575.35 7782.99,1592.01 7782.99,1604.84 7821.5,1643.35 C121.1@7821.5,1647.28
NetC122_1: C122.1 R90.2 R93.2 U15.5 | length 185.7
  Top Layer w10: U15.5@7478.15,1689.69 7491.93,1689.69 7497.76,1695.51 7497.76,1709.29 7506.5,1718.03 R90.2@7506.5,1748.66 7561.5,1748.66 R93.2@7562.87,1747.28 C122.1@7562.87,1797.28
NetC123_1: C123.1 R91.2 R92.2 U15.6 | length 226.3
  Top Layer w10: C123.1@7371.5,1644.69 7372.87,1643.31 R92.2@7421.5,1643.31 ; R91.2@7456.5,1746.42 7456.5,1742.48 7421.5,1707.48 R92.2@7421.5,1643.31 ; U15.6@7478.15,1639.69 7425.12,1639.69 R92.2@7421.5,1643.31
NetC124_2: C124.2 R53.2 R57.2 U10.4 | length 274.7
  Bottom Layer w10: R57.2@6467,4226.24 6467.24,4226 U10.4@6527,4226 6527,4218.13 6533.81,4211.31 6541.69,4211.31 6585,4168 C124.2@6661,4168 R53.2@6713,4168
NetC126_1: C126.1 J5.88 R98.2 | length 126.6
  Top Layer w8: v1(6304.21,3770) 6304.67,3769.55 6304.67,3728.88 J5.88@6305.12,3728.43
  Bottom Layer w8: C126.1@6295,3820 6291.06,3820 6278.62,3807.56 R98.2@6278.62,3770 v1(6304.21,3770)
NetC127_1: C127.1 J5.86 R97.2 | length 199.6
  Top Layer w8: R97.2@6300,3590.28 6339.9,3590.28 6344.9,3590.28 C127.1@6348.19,3590.28 C127.1@6344.9,3593.56 ; J5.86@6336.61,3728.43 J5.86@6339.9,3725.14
  Top Layer w15: C127.1@6339.9,3583 6339.9,3590.28 J5.86@6339.9,3725.14
NetC132_1: C132.1 R56.2 R57.1 | length 118.9
  Bottom Layer w10: R56.2@6409,4177 6465,4177 R57.1@6467,4179 6469,4177 6469,4122.62 C132.1@6471,4120.62
NetC134_1: C134.1 J5.103 R101.2 | length 215.4
  Top Layer w10: R101.2@6004.09,4027.28 C134.1@6054.09,4027.28 C134.1@6053.62,4026.81 ; J5.103@6053.15,3862.28 J5.103@6053.62,3862.76
  Top Layer w15: J5.103@6053.62,3862.76 C134.1@6053.62,4026.81
NetC135_1: C135.1 J5.105 R102.2 | length 245.8
  Top Layer w15: C135.1@5948.74,4075.59 5950.12,4074.21 R102.2@5950.12,4025.59 5954.06,4025.59 5958.37,4021.28 5958.37,4012.79 6019.15,3952 6019.15,3948 6019.31,3947.84 6019.31,3864.63 J5.105@6021.65,3862.28
NetC139_2: C139.2 J5.31 R59.2 | length 186.7
  Top Layer w10: R59.2@7256,3996 C139.2@7306.76,3996
  Top Layer w15: C139.2@7307,3995.76 7307,3991.82 7312.99,3985.83 J5.31@7312.99,3862.28
NetC145_1: C145.1 R103.2 U18.4 | length 134.6
  Top Layer w10: U18.4@2551.02,3377.28 2551.63,3376.67 2634.67,3376.67 R103.2@2635.28,3376.06 2637.87,3373.46 C145.1@2637.87,3327.28
NetC146_1: C146.1 R105.2 U18.5 | length 135.5
  Top Layer w10: U18.5@2551.02,3427.28 2552.24,3426.06 R105.2@2635.28,3426.06 ; C146.1@2634.25,3477.28 2634.25,3427.09 R105.2@2634.67,3426.67
NetD1_1: D1.1 D2.1 R6.2 R10.2 R11.2 R12.2 R13.2 | length 5176.3
  Top Layer w10: v1(2905.16,3076) 2906.07,3075.08 2906.07,3056.02 D2.1@2906.99,3055.1 2870,3018.11 2870,2906 2888.91,2887.09 2905,2887.09 D1.1@2911.81,2880.28
  Top Layer w15: v1(6772,4051) 6816.79,4051 R10.2@6818.28,4052.5 6819.78,4051 R13.2@7113.28,4051 ; R13.2@7113.28,4052.5 7114.78,4051 R6.2@7196.28,4051
  Layer 3 w15: v1(2905.16,3076) 2906,3076.84 2906,3343 3714,4151 6104,4151 6204,4051 v1@6774.16,4051
NetD1_2: D1.2 D3.1 T2.5 | length 198
  Top Layer w10: T2.5@2738.82,2961.5 2748.66,2961.5 2818.39,2891.77 2818.39,2887.09 D1.2@2825.2,2880.28 2828,2877.48 2828,2815.69 D3.1@2834.69,2809
NetD2_2: D2.2 D4.1 T2.6 | length 168.5
  Top Layer w10: T2.6@2738.82,3059.92 2815.56,3059.92 2825.2,3050.28 2825.2,2981.8 D4.1@2832,2975
NetD5_2: D5.2 T3.9 | length 121.3
  Top Layer w10: T3.9@5136.73,1965.31 T3.9@5149.65,1965.31 ; D5.2@5234.08,1993.12 D5.2@5242.87,1984.33
  Top Layer w20: T3.9@5149.65,1965.31 5177.46,1993.12 D5.2@5234.08,1993.12
NetD6_1: D6.1 R33.1 | length 91.5
  Top Layer w10: R33.1@4196.61,1909.33 4254.6,1909.33 4275.19,1888.74 D6.1@4275.19,1884.33
NetD6_2: D6.2 R35.2 T3.3 | length 212.4
  Top Layer w10: R35.2@4394.8,1804.33 4393.3,1805.82 4393.3,1884.33 D6.2@4413.3,1864.33 ; T3.3@4497.91,1847.91 T3.3@4506.49,1839.33
  Top Layer w20: D6.2@4413.3,1864.33 4441.61,1864.33 4458.03,1847.91 T3.3@4497.91,1847.91
NetD8_2: D8.2 R34.2 T3.5 | length 285.2
  Top Layer w10: R34.2@4394.6,1579.33 4401.61,1572.32 4401.61,1464.76 D8.2@4447.04,1419.33 ; R34.2@4406.3,1579.33 4414.33,1587.36
  Top Layer w20: 4414.33,1587.36 T3.5@4506.49,1587.36
NetJ4_1: J4.1 R74.2 | length 1684.7
  Top Layer w6: R74.2@2013,3487.79 R74.2@2013.5,3487.28
  Top Layer w10: R74.2@2013,3487.79 v1(2013,3517)
  Layer 2 w20: J4.1@891.5,4227.28 1023.78,4095 1835,4095 2013,3917 v1@2013,3512.24
NetL4_1: L4.1 U9.7 | length 114.2
  Top Layer w10: U9.7@1859.84,4027.45 1861.73,4027.45 1861.92,4027.64 1872.64,4027.64 1888.07,4043.07 1888.07,4052.09 1908.66,4072.68 L4.1@1950,4072.68
NetL7_1: L7.1 U16.7 | length 115.3
  Top Layer w10: L7.1@6408.82,3542.28 6408.82,3500.94 6429.41,3480.35 6433.43,3480.35 6441.5,3472.28 6452.05,3461.73 6452.05,3447.36 U16.7@6452.13,3447.28
NetQ1_4: Q1.4 Q2.4 Q3.4 Q8.4 R37.1 R39.2 | length 1123.6
  Top Layer w20: R39.2@7701.5,1192.28 Q2.4@7746.5,1192.28 7781.5,1192.28 7786.5,1197.28 ; Q8.4@7744.41,550.16 7774.37,550.16 7786.5,562.28 7786.5,762.28 ; Q3.4@7745.43,765.16 7783.62,765.16 7786.5,762.28 ; Q1.4@7746.5,980.16 7784.37,980.16 7786.5,982.28 ; R37.1@7789.49,1467.28 7786.5,1464.29 7786.5,1197.28 ; 7786.5,762.28 7786.5,982.28 ; 7786.5,982.28 7786.5,1197.28
NetQ4_4: Q4.4 Q5.4 Q6.4 Q7.4 R36.2 R38.2 | length 1158.7
  Top Layer w20: R38.2@7696.5,2603.66 7697.99,2605.16 Q4.4@7746.5,2605.16 7783.62,2605.16 7786.5,2602.28 ; Q5.4@7746.5,1940.16 7774.37,1940.16 7786.5,1952.28 7786.5,2167.28 ; Q6.4@7746.5,2165.16 7784.37,2165.16 7786.5,2167.28 ; Q7.4@7746.5,2390.16 7784.37,2390.16 7786.5,2392.28 ; R36.2@7822.99,2877.28 7822.99,2838.78 7786.5,2802.28 7786.5,2602.28 ; 7786.5,2167.28 7786.5,2392.28 ; 7786.5,2392.28 7786.5,2602.28
NetQ9_4: Q9.4 Q10.4 Q11.4 Q16.4 R48.1 R52.2 | length 1144.5
  Top Layer w20: R52.2@7296.5,1195.04 7296.61,1195.16 Q10.4@7349.02,1195.16 7386.87,1195.16 7391.5,1199.78 ; Q16.4@7344.09,767.28 7386.5,767.28 7391.5,772.28 ; Q11.4@7345.16,554.41 7345.2,554.45 7371.45,554.45 7391.5,574.5 7391.5,772.28 ; Q9.4@7345.55,982.28 7391.5,982.28 ; R48.1@7406.5,1465.79 7406.5,1432.28 7391.5,1417.28 7391.5,1199.78 ; 7391.5,772.28 7391.5,982.28 ; 7391.5,982.28 7391.5,1199.78
NetQ12_4: Q12.4 Q13.4 Q14.4 Q15.4 R47.2 R51.2 | length 1151.8
  Top Layer w20: R51.2@7311.5,2608.66 7312.99,2610.16 Q15.4@7359.02,2610.16 7399.02,2610.16 ; Q13.4@7358.07,2162.28 7399.02,2162.28 ; Q12.4@7359.02,1939.41 7365.91,1939.41 7399.02,1972.52 7399.02,2162.28 ; Q14.4@7359.02,2385.16 7395.02,2385.16 7399.02,2389.15 ; R47.2@7441.5,2882.28 7441.5,2881.3 7399.02,2838.82 7399.02,2610.16 ; 7399.02,2162.28 7399.02,2389.15 ; 7399.02,2389.15 7399.02,2610.16
NetR1_1: R1.1 R2.2 | length 77.9
  Bottom Layer w10: R1.1@224.09,1642.28 R2.2@302.01,1642.28
NetR2_1: R2.1 R4.2 | length 97.1
  Bottom Layer w10: R2.1@416.18,1642.28 499.09,1642.28 R4.2@509.09,1632.28
NetR4_1: R4.1 R7.2 | length 101.7
  Bottom Layer w10: R4.1@509.09,1746.46 597.83,1746.46 R7.2@607.01,1737.28
NetR15_1: R15.1 R17.2 | length 108
  Bottom Layer w10: R15.1@1289.17,3550 R15.1@1293.31,3554.13
  Bottom Layer w20: R15.1@1293.31,3554.13 R17.2@1395.47,3554.13
NetR17_1: R17.1 R20.2 | length 80.8
  Bottom Layer w20: R17.1@1507.09,3550 R20.2@1587.91,3550
NetR19_1: R19.1 U4.6 | length 5113.6
  Top Layer w10: R19.1@7428.94,4227.28 R19.1@7432.87,4227.28 R19.1@7431.5,4228.66
  Top Layer w20: U4.6@2579.17,3862.28 v1(2620.47,3862.28) ; R19.1@7431.5,4228.66 v1(7431.5,4252.28)
  Layer 3 w20: v1(2620.47,3862.28) 2669.19,3911 3125.21,3911 3551.21,4337 7346.78,4337 v1(7431.5,4252.28)
NetR20_1: R20.1 R22.1 R27.2 | length 320.3
  Bottom Layer w20: R20.1@1722.09,3550 1727.99,3555.91 1881.57,3555.91 1941.77,3616.1 1944.29,3616.1 R27.2@1948.35,3620.16 ; R27.2@1950.47,3625.79 R22.1@2015.47,3625.79
NetR21_1: R21.1 U4.7 | length 5237.6
  Top Layer w20: U4.7@2578.88,3912 v1(2619,3912) ; v1(7573.5,4237.28) R21.1@7599.09,4237.28
  Layer 2 w20: v1(2619,3912) 3126.21,3912 3551.21,4337 7473.79,4337 v1(7573.5,4237.28)
NetR23_1: R23.1 U5.6 | length 5702.3
  Top Layer w20: R23.1@7451.5,3444.53 v1(7451.5,3470.12)
  Layer 2 w20: v1(2620.47,3762.28) 2670.47,3812.28 3160.47,3812.28 3603.19,4255 7057.76,4255 7501.5,3811.26 7501.5,3518.31 7455.65,3472.46 7455.11,3472.46 v1@7451.92,3469.27
  Bottom Layer w20: U5.6@2575.47,3762.28 v1(2620.47,3762.28)
NetR26_1: R26.1 U5.7 | length 5814.8
  Top Layer w20: v1(7501.5,3371.69) R26.1@7501.5,3391.77
  Layer 3 w20: v1(2619.68,3712.26) 2719.7,3812.28 3160.47,3812.28 3602.19,4254 7058,4254 7501.5,3810.5 v1(7501.5,3371.69)
  Bottom Layer w20: U5.7@2553.67,3712.27 v1(2619.68,3712.26)
NetR35_1: R35.1 U6.8 | length 89
  Top Layer w10: U6.8@4258.3,1749.33 4259.72,1750.75 4291.53,1750.75 4315.43,1774.64 4315.43,1775.63 4329.13,1789.33 R35.1@4330.11,1789.33
NetR42_1: R42.1 R44.2 U7.3 | length 136.1
  Bottom Layer w8: R42.1@5208.11,1360.86 R42.1@5208.7,1360.27
  Bottom Layer w10: R42.1@5208.7,1360.27 U7.3@5343.97,1360.27
NetR43_1: R43.1 R45.2 U8.3 | length 89.8
  Top Layer w10: R43.1@5251.61,1827.32 5261.02,1836.73 v1(5280.15,1836.73)
  Bottom Layer w10: v1(5280.15,1836.73) U8.3@5337.48,1836.73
